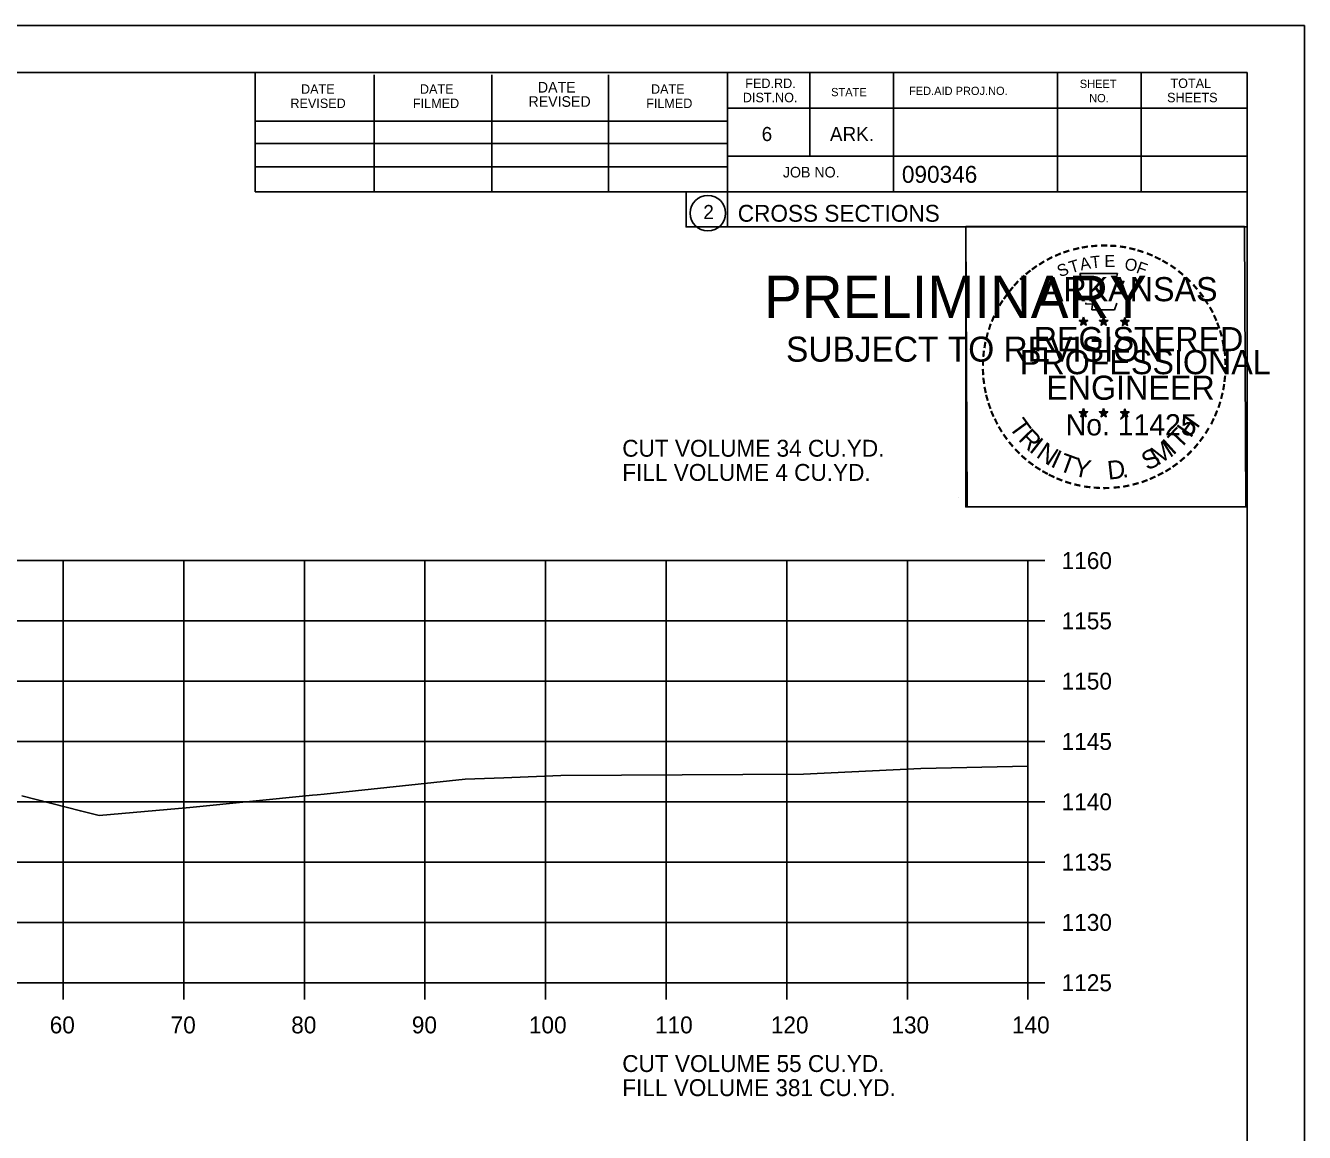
# Model space of a CAD drawing. Extents: x 1368971 to 1374497, y 378717 to 381839.
# Drawn here: x 1369198.5 to 1369304.5, y 381143 to 381234.8 of the extents above; entities that cross this region are included whole.
import ezdxf

# ---------------------------------------------------------------- set-up
doc = ezdxf.new("R2010")
doc.units = 0
for name, color, linetype in [('R_Axis', 7, 'Continuous'), ('R_Axis Annot', 7, 'Continuous'), ('R_Border', 7, 'Continuous'), ('R_Border PE', 7, 'Continuous'), ('R_Border Prem', 7, 'Continuous'), ('R_Exist Surface', 7, 'Continuous'), ('R_Grid', 7, 'Continuous'), ('R_No Plot', 7, 'Continuous')]:
    doc.layers.add(name, color=color, linetype=linetype)

msp = doc.modelspace()

# ---------------------------------------------------------------- linework, layer by layer
at = {"layer": 'R_Axis'}
for p, q in [((1369281.6, 381155.44), (1369281.6, 381190.44)), ((1369283, 381190.44), (1369281.6, 381190.44)), ((1369283, 381185.44), (1369281.6, 381185.44)), ((1369283, 381180.44), (1369281.6, 381180.44)), ((1369283, 381175.44), (1369281.6, 381175.44)), ((1369283, 381170.44), (1369281.6, 381170.44)), ((1369283, 381165.44), (1369281.6, 381165.44)), ((1369283, 381160.44), (1369281.6, 381160.44)), ((1369001.6, 381155.44), (1369281.6, 381155.44)), ((1369201.6, 381154.04), (1369201.6, 381155.44)), ((1369211.6, 381154.04), (1369211.6, 381155.44)), ((1369221.6, 381154.04), (1369221.6, 381155.44)), ((1369231.6, 381154.04), (1369231.6, 381155.44)), ((1369241.6, 381154.04), (1369241.6, 381155.44)), ((1369251.6, 381154.04), (1369251.6, 381155.44)), ((1369261.6, 381154.04), (1369261.6, 381155.44)), ((1369271.6, 381154.04), (1369271.6, 381155.44)), ((1369281.6, 381154.04), (1369281.6, 381155.44)), ((1369283, 381155.44), (1369281.6, 381155.44))]:
    msp.add_line(p, q, dxfattribs=at)
at = {"layer": 'R_Border'}
for p, q in [((1368983.6, 381230.9), (1369299.78, 381230.9)), ((1369217.52, 381221.02), (1369217.52, 381230.9)), ((1369227.38, 381221.02), (1369227.38, 381230.7)), ((1369237.14, 381221.02), (1369237.14, 381230.7)), ((1369246.82, 381221.02), (1369246.82, 381230.7)), ((1369256.68, 381230.9), (1369256.68, 381218.1)), ((1369263.52, 381230.9), (1369263.52, 381223.96)), ((1369270.46, 381230.9), (1369270.46, 381221.02)), ((1369284.04, 381230.9), (1369284.04, 381221.02)), ((1369290.98, 381230.9), (1369290.98, 381221.02)), ((1369299.78, 381025.44), (1369299.78, 381230.9)), ((1369299.78, 381227.96), (1369256.68, 381227.96)), ((1369299.78, 381227.98), (1369299.78, 381227.98)), ((1369217.52, 381226.88), (1369256.68, 381226.88)), ((1369217.52, 381225.02), (1369256.68, 381225.02)), ((1369299.78, 381223.96), (1369256.68, 381223.96)), ((1369259.64, 381223.96), (1369299.78, 381223.96)), ((1369217.52, 381221.02), (1369217.52, 381223.08)), ((1369217.52, 381223.08), (1369256.68, 381223.08)), ((1369299.78, 381221.02), (1369217.52, 381221.02)), ((1369256.68, 381218.1), (1369299.78, 381218.1))]:
    msp.add_line(p, q, dxfattribs=at)
msp.add_circle((1369255.06, 381219.24), 1.47, dxfattribs=at)
at = {"layer": 'R_Border PE'}
for p, q in [((1369285.86, 381210.35), (1369286.21, 381210.24)), ((1369285.86, 381210.35), (1369286.11, 381210.31)), ((1369285.86, 381210.35), (1369286.1, 381210.23)), ((1369285.99, 381209.95), (1369286.21, 381210.24)), ((1369285.99, 381209.95), (1369286.12, 381210.19)), ((1369285.99, 381209.95), (1369286.21, 381210.16)), ((1369286.21, 381210.61), (1369286.17, 381210.36)), ((1369286.21, 381210.24), (1369286.21, 381210.61)), ((1369286.21, 381210.61), (1369286.26, 381210.36)), ((1369286.56, 381210.35), (1369286.21, 381210.24)), ((1369286.42, 381209.95), (1369286.21, 381210.24)), ((1369286.42, 381209.95), (1369286.21, 381210.16)), ((1369286.56, 381210.35), (1369286.27, 381210.31)), ((1369286.42, 381209.95), (1369286.29, 381210.24)), ((1369286.56, 381210.35), (1369286.35, 381210.25)), ((1369287.53, 381210.35), (1369287.88, 381210.24)), ((1369287.53, 381210.35), (1369287.78, 381210.31)), ((1369287.53, 381210.35), (1369287.77, 381210.23)), ((1369287.66, 381209.95), (1369287.88, 381210.24)), ((1369287.66, 381209.95), (1369287.79, 381210.19)), ((1369287.66, 381209.95), (1369287.88, 381210.16)), ((1369287.88, 381210.61), (1369287.84, 381210.36)), ((1369287.88, 381210.24), (1369287.88, 381210.61)), ((1369287.88, 381210.61), (1369287.93, 381210.36)), ((1369288.23, 381210.35), (1369287.88, 381210.24)), ((1369288.09, 381209.95), (1369287.88, 381210.24)), ((1369288.09, 381209.95), (1369287.88, 381210.16)), ((1369288.23, 381210.35), (1369287.94, 381210.31)), ((1369288.09, 381209.95), (1369287.96, 381210.24)), ((1369288.23, 381210.35), (1369288.02, 381210.25)), ((1369289.3, 381210.34), (1369289.64, 381210.23)), ((1369289.3, 381210.34), (1369289.55, 381210.3)), ((1369289.3, 381210.34), (1369289.53, 381210.22)), ((1369289.43, 381209.93), (1369289.64, 381210.23)), ((1369289.43, 381209.93), (1369289.55, 381210.18)), ((1369289.43, 381209.93), (1369289.64, 381210.15)), ((1369289.64, 381210.6), (1369289.6, 381210.34)), ((1369289.64, 381210.23), (1369289.64, 381210.6)), ((1369289.64, 381210.6), (1369289.69, 381210.35)), ((1369289.99, 381210.34), (1369289.64, 381210.23)), ((1369289.86, 381209.93), (1369289.64, 381210.23)), ((1369289.86, 381209.93), (1369289.64, 381210.15)), ((1369289.99, 381210.34), (1369289.71, 381210.29)), ((1369289.86, 381209.93), (1369289.72, 381210.23)), ((1369289.99, 381210.34), (1369289.79, 381210.24)), ((1369285.86, 381202.78), (1369286.21, 381202.67)), ((1369285.86, 381202.78), (1369286.11, 381202.74)), ((1369285.86, 381202.78), (1369286.09, 381202.66)), ((1369285.99, 381202.37), (1369286.21, 381202.67)), ((1369285.99, 381202.37), (1369286.12, 381202.62)), ((1369285.99, 381202.37), (1369286.2, 381202.59)), ((1369286.21, 381203.04), (1369286.17, 381202.78)), ((1369286.42, 381202.37), (1369286.2, 381202.59)), ((1369286.21, 381202.67), (1369286.21, 381203.04)), ((1369286.21, 381203.04), (1369286.26, 381202.79)), ((1369286.55, 381202.78), (1369286.21, 381202.67)), ((1369286.42, 381202.37), (1369286.21, 381202.67)), ((1369286.55, 381202.78), (1369286.27, 381202.73)), ((1369286.42, 381202.37), (1369286.28, 381202.66)), ((1369286.55, 381202.78), (1369286.35, 381202.68)), ((1369287.53, 381202.78), (1369287.88, 381202.67)), ((1369287.53, 381202.78), (1369287.78, 381202.74)), ((1369287.53, 381202.78), (1369287.76, 381202.66)), ((1369287.66, 381202.37), (1369287.88, 381202.67)), ((1369287.66, 381202.37), (1369287.79, 381202.62)), ((1369287.66, 381202.37), (1369287.87, 381202.59)), ((1369287.88, 381203.04), (1369287.83, 381202.78)), ((1369288.09, 381202.37), (1369287.87, 381202.59)), ((1369287.88, 381202.67), (1369287.88, 381203.04)), ((1369287.88, 381203.04), (1369287.92, 381202.79)), ((1369288.22, 381202.78), (1369287.88, 381202.67)), ((1369288.09, 381202.37), (1369287.88, 381202.67)), ((1369288.22, 381202.78), (1369287.94, 381202.73)), ((1369288.09, 381202.37), (1369287.95, 381202.66)), ((1369288.22, 381202.78), (1369288.02, 381202.68)), ((1369289.29, 381202.77), (1369289.64, 381202.66)), ((1369289.29, 381202.77), (1369289.55, 381202.73)), ((1369289.29, 381202.77), (1369289.53, 381202.65)), ((1369289.43, 381202.36), (1369289.64, 381202.66)), ((1369289.43, 381202.36), (1369289.55, 381202.61)), ((1369289.43, 381202.36), (1369289.64, 381202.58)), ((1369289.64, 381203.03), (1369289.6, 381202.77)), ((1369289.64, 381202.66), (1369289.64, 381203.03)), ((1369289.64, 381203.03), (1369289.69, 381202.78)), ((1369289.99, 381202.77), (1369289.64, 381202.66)), ((1369289.86, 381202.36), (1369289.64, 381202.66)), ((1369289.86, 381202.36), (1369289.64, 381202.58)), ((1369289.99, 381202.77), (1369289.7, 381202.72)), ((1369289.86, 381202.36), (1369289.72, 381202.65)), ((1369289.99, 381202.77), (1369289.79, 381202.67))]:
    msp.add_line(p, q, dxfattribs=at)
for points in [[(1369285.9, 381214.23), (1369286.17, 381213.41)], [(1369289.41, 381213.31), (1369289.56, 381213.59), (1369288.87, 381213.57), (1369289.02, 381214.23), (1369285.9, 381214.23)], [(1369286.39, 381211.81), (1369286.39, 381211.72), (1369286.96, 381211.7), (1369286.9, 381211.23), (1369288.77, 381211.23), (1369288.97, 381211.77)], [(1369286.21, 381210.61), (1369286.42, 381209.95), (1369285.86, 381210.35), (1369286.56, 381210.35), (1369285.99, 381209.95), (1369286.21, 381210.61)], [(1369287.88, 381210.61), (1369288.09, 381209.95), (1369287.53, 381210.35), (1369288.23, 381210.35), (1369287.66, 381209.95), (1369287.88, 381210.61)], [(1369289.64, 381210.6), (1369289.86, 381209.93), (1369289.3, 381210.34), (1369289.99, 381210.34), (1369289.43, 381209.93), (1369289.64, 381210.6)], [(1369286.21, 381203.04), (1369286.42, 381202.37), (1369285.86, 381202.78), (1369286.55, 381202.78), (1369285.99, 381202.37), (1369286.21, 381203.04)], [(1369287.88, 381203.04), (1369288.09, 381202.37), (1369287.53, 381202.78), (1369288.22, 381202.78), (1369287.66, 381202.37), (1369287.88, 381203.04)], [(1369289.64, 381203.03), (1369289.86, 381202.36), (1369289.29, 381202.77), (1369289.99, 381202.77), (1369289.43, 381202.36), (1369289.64, 381203.03)]]:
    msp.add_lwpolyline(points, dxfattribs=at)
for centre, radius in [((1369286.21, 381210.24), 0.172), ((1369286.21, 381210.24), 0.145), ((1369286.21, 381210.24), 0.116), ((1369286.21, 381210.24), 0.0991), ((1369286.21, 381210.24), 0.0747), ((1369286.21, 381210.24), 0.0495), ((1369286.21, 381210.24), 0.0296), ((1369287.88, 381210.24), 0.172), ((1369287.88, 381210.24), 0.145), ((1369287.88, 381210.24), 0.116), ((1369287.88, 381210.24), 0.0991), ((1369287.88, 381210.24), 0.0747), ((1369287.88, 381210.24), 0.0495), ((1369287.88, 381210.24), 0.0296), ((1369289.64, 381210.23), 0.172), ((1369289.64, 381210.23), 0.145), ((1369289.64, 381210.23), 0.116), ((1369289.64, 381210.23), 0.0991), ((1369289.64, 381210.23), 0.0747), ((1369289.64, 381210.23), 0.0495), ((1369289.64, 381210.23), 0.0296), ((1369286.21, 381202.67), 0.172), ((1369286.21, 381202.67), 0.145), ((1369286.21, 381202.67), 0.116), ((1369286.21, 381202.67), 0.0991), ((1369286.21, 381202.67), 0.0747), ((1369286.21, 381202.67), 0.0495), ((1369286.21, 381202.67), 0.0296), ((1369287.87, 381202.67), 0.172), ((1369287.87, 381202.67), 0.145), ((1369287.87, 381202.67), 0.116), ((1369287.87, 381202.67), 0.0991), ((1369287.87, 381202.67), 0.0747), ((1369287.87, 381202.67), 0.0495), ((1369287.87, 381202.67), 0.0296), ((1369289.64, 381202.66), 0.172), ((1369289.64, 381202.66), 0.145), ((1369289.64, 381202.66), 0.116), ((1369289.64, 381202.66), 0.0991), ((1369289.64, 381202.66), 0.0747), ((1369289.64, 381202.66), 0.0495), ((1369289.64, 381202.66), 0.0296)]:
    msp.add_circle(centre, radius, dxfattribs=at)
at = {"layer": 'R_Exist Surface'}
msp.add_lwpolyline([(1369198.17, 381170.93), (1369203.03, 381169.68), (1369204.59, 381169.3), (1369212.1, 381169.96), (1369222.28, 381170.98), (1369222.66, 381171.01), (1369223.23, 381171.07), (1369234.94, 381172.32), (1369238.13, 381172.44), (1369242.87, 381172.62), (1369262.98, 381172.72), (1369272.73, 381173.21), (1369281.6, 381173.4)], dxfattribs=at)
at = {"layer": 'R_Grid'}
for p, q in [((1369001.6, 381190.44), (1369281.6, 381190.44)), ((1369201.6, 381155.44), (1369201.6, 381190.44)), ((1369211.6, 381155.44), (1369211.6, 381190.44)), ((1369221.6, 381155.44), (1369221.6, 381190.44)), ((1369231.6, 381155.44), (1369231.6, 381190.44)), ((1369241.6, 381155.44), (1369241.6, 381190.44)), ((1369251.6, 381155.44), (1369251.6, 381190.44)), ((1369261.6, 381155.44), (1369261.6, 381190.44)), ((1369271.6, 381155.44), (1369271.6, 381190.44)), ((1369281.6, 381155.44), (1369281.6, 381190.44)), ((1369001.6, 381185.44), (1369281.6, 381185.44)), ((1369001.6, 381180.44), (1369281.6, 381180.44)), ((1369001.6, 381175.44), (1369281.6, 381175.44)), ((1369001.6, 381170.44), (1369281.6, 381170.44)), ((1369001.6, 381165.44), (1369281.6, 381165.44)), ((1369001.6, 381160.44), (1369281.6, 381160.44)), ((1369001.6, 381155.44), (1369281.6, 381155.44))]:
    msp.add_line(p, q, dxfattribs=at)
at = {"layer": 'R_No Plot'}
for p, q in [((1368971.2, 381234.79), (1369304.53, 381234.79)), ((1369275.81, 381195.64), (1369275.81, 381195.64))]:
    msp.add_line(p, q, dxfattribs=at)
for points in [[(1368971.19, 381234.79), (1369304.53, 381234.79), (1369304.53, 381021.46), (1368971.19, 381021.46)], [(1369217.52, 381230.9), (1369217.52, 381221.02), (1369253.25, 381221.02), (1369253.25, 381218.1), (1369276.45, 381218.1), (1369276.45, 381194.89), (1369299.78, 381194.89), (1369299.78, 381025.44), (1368983.6, 381025.44), (1368983.6, 381230.9)], [(1369276.45, 381218.13), (1369299.55, 381218.13), (1369299.66, 381194.89), (1369276.56, 381194.89)]]:
    msp.add_lwpolyline(points, close=True, dxfattribs=at)

# ---------------------------------------------------------------- texts
at = {"layer": 'R_Axis Annot'}
for s, p in [('CUT VOLUME 34 CU.YD.', (1369247.96, 381199.05)), ('FILL VOLUME 4 CU.YD.', (1369247.96, 381197.05)), ('1160', (1369284.4, 381189.74)), ('1155', (1369284.4, 381184.74)), ('1150', (1369284.4, 381179.74)), ('1145', (1369284.4, 381174.74)), ('1140', (1369284.4, 381169.74)), ('1135', (1369284.4, 381164.74)), ('1130', (1369284.4, 381159.74)), ('1125', (1369284.4, 381154.74)), ('60', (1369200.48, 381151.24)), ('70', (1369210.51, 381151.24)), ('80', (1369220.51, 381151.24)), ('90', (1369230.51, 381151.24)), ('100', (1369240.22, 381151.24)), ('110', (1369250.68, 381151.24)), ('120', (1369260.28, 381151.24)), ('130', (1369270.28, 381151.24)), ('140', (1369280.28, 381151.24)), ('CUT VOLUME 55 CU.YD.', (1369247.96, 381148.04)), ('FILL VOLUME 381 CU.YD.', (1369247.96, 381146.04))]:
    msp.add_text(s, height=1.4, dxfattribs=at).set_placement(p)
at = {"layer": 'R_Border'}
for s, height, p in [('DATE', 0.782, (1369221.32, 381229.14)), ('DATE', 0.782, (1369231.18, 381229.14)), ('DATE', 0.879, (1369240.96, 381229.24)), ('DATE', 0.782, (1369250.34, 381229.14)), ('FED.RD.', 0.782, (1369258.16, 381229.62)), ('SHEET', 0.684, (1369285.9, 381229.62)), ('TOTAL', 0.782, (1369293.42, 381229.62)), ('REVISED', 0.879, (1369240.18, 381228.06)), ('DIST.NO.', 0.782, (1369257.96, 381228.44)), ('STATE', 0.684, (1369265.28, 381228.94)), ('FED.AID PROJ.NO.', 0.684, (1369271.74, 381229.04)), ('NO.', 0.684, (1369286.68, 381228.44)), ('SHEETS', 0.782, (1369293.14, 381228.44)), ('REVISED', 0.782, (1369220.44, 381227.96)), ('FILMED', 0.782, (1369230.6, 381227.96)), ('FILMED', 0.782, (1369249.94, 381227.96)), ('6', 1.17, (1369259.52, 381225.22)), ('ARK.', 1.172, (1369265.18, 381225.22)), ('JOB NO.', 0.879, (1369261.28, 381222.2)), ('2', 1.17, (1369254.68, 381218.75)), ('CROSS SECTIONS', 1.4, (1369257.54, 381218.53))]:
    msp.add_text(s, height=height, dxfattribs=at).set_placement(p)
msp.add_text('090346', height=1.4, rotation=360, dxfattribs=at).set_placement((1369271.15, 381221.76))
at = {"layer": 'R_Border PE'}
for s, height, rotation, p in [('-', 1.6, 19.1761, (1369284.65, 381215.36)), ('-', 1.6, 13.6301, (1369285.4, 381215.6)), ('-', 1.6, 10.2193, (1369286.08, 381215.76)), ('-', 1.6, 5.8968, (1369286.81, 381215.87)), ('-', 1.6, 0.1862, (1369287.58, 381215.94)), ('-', 1.6, 357.743, (1369288.3, 381215.93)), ('-', 1.6, 352.1617, (1369289.05, 381215.88)), ('-', 1.6, 347.2049, (1369289.77, 381215.76)), ('-', 1.6, 342.3362, (1369290.4, 381215.61)), ('-', 1.6, 34.0636, (1369282.79, 381214.4)), ('-', 1.6, 28.7918, (1369283.38, 381214.77)), ('-', 1.6, 24.3072, (1369284.02, 381215.09)), ('S', 1, 21.594, (1369284.26, 381213.91)), ('T', 1, 16.4036, (1369285.17, 381214.24)), ('A', 1, 11.2132, (1369286, 381214.49)), ('T', 1, 6.0228, (1369286.85, 381214.66)), ('E', 1, 0.8323, (1369287.95, 381214.77)), ('O', 1, 350.4515, (1369289.56, 381214.56)), ('F', 1, 340.0707, (1369290.51, 381214.33)), ('-', 1.6, 337.8551, (1369291.14, 381215.38)), ('-', 1.6, 334.1211, (1369291.77, 381215.11)), ('-', 1.6, 329.6409, (1369292.35, 381214.83)), ('-', 1.6, 42.9622, (1369281.3, 381213.21)), ('-', 1.6, 38.9507, (1369281.73, 381213.63)), ('-', 1.6, 36.2317, (1369282.21, 381214.01)), ('-', 1.6, 325.8627, (1369292.99, 381214.47)), ('-', 1.6, 320.5297, (1369293.6, 381214.04)), ('-', 1.6, 315.5786, (1369294.2, 381213.55)), ('-', 1.6, 50.6142, (1369280.45, 381212.25)), ('-', 1.6, 48.423, (1369280.85, 381212.74)), ('-', 1.6, 309.8797, (1369294.77, 381213)), ('-', 1.6, 58.0706, (1369279.71, 381211.16)), ('-', 1.6, 54.2325, (1369280.04, 381211.68)), ('-', 1.6, 306.6522, (1369295.29, 381212.4)), ('-', 1.4, 303.6753, (1369295.78, 381211.83)), ('-', 1.6, 62.8713, (1369279.4, 381210.54)), ('-', 1.6, 299.6684, (1369296.1, 381211.23)), ('-', 1.6, 294.6628, (1369296.42, 381210.62)), ('-', 1.6, 72.3945, (1369278.92, 381209.3)), ('-', 1.6, 67.7743, (1369279.14, 381209.93)), ('-', 1.6, 290.5728, (1369296.68, 381210.04)), ('-', 1.6, 75.461, (1369278.72, 381208.59)), ('-', 1.6, 285.1233, (1369296.91, 381209.46)), ('-', 1.6, 280.5493, (1369297.11, 381208.72)), ('-', 1.6, 85.1863, (1369278.51, 381207.18)), ('-', 1.6, 81.2013, (1369278.59, 381207.87)), ('-', 1.6, 276.5962, (1369297.27, 381207.95)), ('-', 1.6, 89.0622, (1369278.49, 381206.48)), ('-', 1.6, 274.3301, (1369297.33, 381207.23)), ('-', 1.6, 94.1959, (1369278.52, 381205.76)), ('-', 1.6, 98.9479, (1369278.6, 381205.09)), ('-', 1.6, 263.5172, (1369297.35, 381205.93)), ('-', 1.6, 269.9407, (1369297.37, 381206.59)), ('-', 1.6, 101.7149, (1369278.73, 381204.36)), ('-', 1.6, 260.9953, (1369297.28, 381205.27)), ('-', 1.6, 105.4578, (1369278.89, 381203.76)), ('-', 1.6, 109.0874, (1369279.11, 381203.13)), ('-', 1.6, 252.8681, (1369296.99, 381203.88)), ('-', 1.6, 255.7626, (1369297.17, 381204.6)), ('-', 1.6, 114.0643, (1369279.36, 381202.53)), ('T', 1.54, 306.0406, (1369279.97, 381201.51)), ('H', 1.54, 54.6088, (1369295.09, 381200.54)), ('-', 1.6, 247.8887, (1369296.76, 381203.2)), ('-', 1.6, 115.7288, (1369279.67, 381201.92)), ('-', 1.6, 120.4471, (1369280.02, 381201.33)), ('R', 1.54, 314.005, (1369280.73, 381200.46)), ('T', 1.54, 46.6444, (1369294.2, 381199.6)), ('-', 1.6, 239.0712, (1369296.11, 381201.82)), ('-', 1.6, 244.6197, (1369296.5, 381202.57)), ('-', 1.6, 125.8934, (1369280.43, 381200.77)), ('-', 1.6, 130.7181, (1369280.89, 381200.22)), ('I', 1.54, 321.9694, (1369281.63, 381199.53)), ('N', 1.54, 326.5002, (1369282.2, 381199.06)), ('M', 1.54, 32.6563, (1369292.35, 381198.28)), ('I', 1.54, 42.1136, (1369293.63, 381199.12)), ('-', 1.6, 233.8452, (1369295.71, 381201.17)), ('-', 1.6, 134.2238, (1369281.41, 381199.67)), ('-', 1.6, 138.9338, (1369281.93, 381199.21)), ('I', 1.54, 335.3603, (1369283.4, 381198.27)), ('T', 1.54, 339.8912, (1369284.07, 381197.94)), ('S', 1.54, 26.9312, (1369291.51, 381197.87)), ('-', 1.6, 225.7653, (1369294.8, 381200.04)), ('-', 1.6, 231.2538, (1369295.28, 381200.6)), ('-', 1.6, 144.6463, (1369282.49, 381198.8)), ('-', 1.6, 148.0898, (1369283.05, 381198.43)), ('Y', 1.54, 347.8556, (1369285.28, 381197.5)), ('D', 1.54, 6.3969, (1369288.27, 381197.14)), ('-', 1.6, 212.2491, (1369293.19, 381198.67)), ('-', 1.6, 215.7363, (1369293.73, 381199.06)), ('-', 1.6, 221.0851, (1369294.27, 381199.53)), ('-', 1.6, 151.5704, (1369283.63, 381198.11)), ('-', 1.6, 154.6002, (1369284.15, 381197.86)), ('-', 1.6, 158.5612, (1369284.77, 381197.61)), ('-', 1.6, 162.7983, (1369285.46, 381197.39)), ('.', 1.54, 13.7642, (1369289.46, 381197.27)), ('-', 1.6, 200.7184, (1369291.39, 381197.73)), ('-', 1.6, 204.2516, (1369292.01, 381198.01)), ('-', 1.6, 207.3568, (1369292.63, 381198.33)), ('-', 1.6, 167.5555, (1369286.18, 381197.23)), ('-', 1.6, 173.1155, (1369286.95, 381197.12)), ('-', 1.6, 176.5183, (1369287.7, 381197.07)), ('-', 1.6, 181.5918, (1369288.44, 381197.08)), ('-', 1.6, 185.8167, (1369289.25, 381197.16)), ('-', 1.6, 191.2858, (1369289.98, 381197.29)), ('-', 1.6, 195.4743, (1369290.71, 381197.49))]:
    msp.add_text(s, height=height, rotation=rotation, dxfattribs=at).set_placement(p)
for s, height, p in [('ARKANSAS', 2, (1369282.76, 381211.94)), ('REGISTERED', 2, (1369282.08, 381207.8)), ('DWB', 0.01, (1369286.2, 381210.24)), ('DWB', 0.01, (1369287.87, 381210.24)), ('DWB', 0.01, (1369289.63, 381210.23)), ('PROFESSIONAL', 2, (1369280.93, 381205.89)), ('ENGINEER', 2, (1369283.12, 381203.77)), ('No. 11425', 1.757, (1369284.74, 381200.82)), ('DWB', 0.01, (1369286.19, 381202.67)), ('DWB', 0.01, (1369287.86, 381202.67)), ('DWB', 0.01, (1369289.63, 381202.66))]:
    msp.add_text(s, height=height, dxfattribs=at).set_placement(p)
at = {"layer": 'R_Border Prem'}
for s, height, p in [('PRELIMINARY', 3.5, (1369259.73, 381210.56)), ('DWB', 0.01, (1369260.47, 381212.41)), ('SUBJECT TO REVISION', 2.0751, (1369261.54, 381206.93))]:
    msp.add_text(s, height=height, dxfattribs=at).set_placement(p)

doc.saveas('drawing.dxf')
